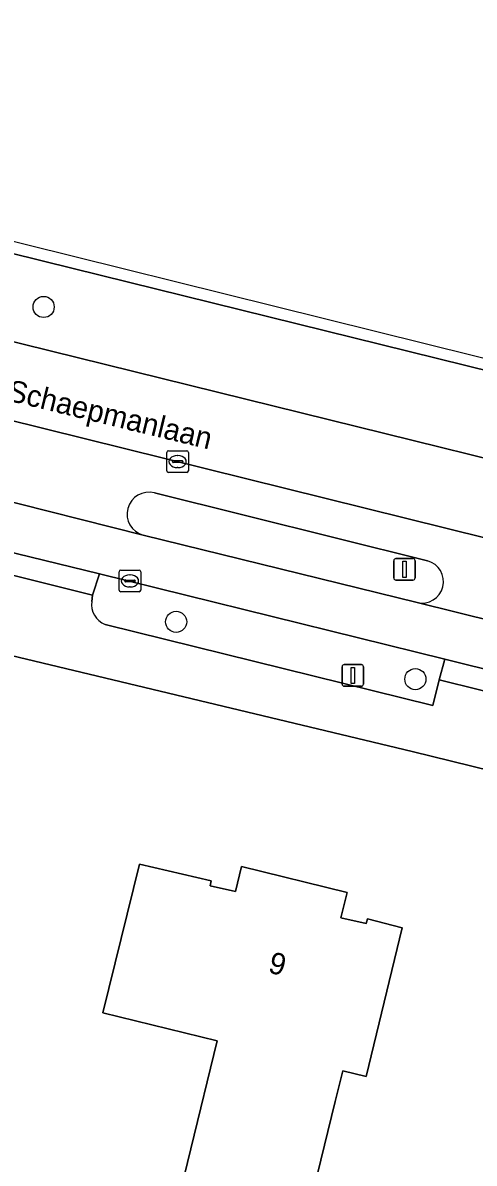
# Model space of a CAD drawing. Extents: x 161139 to 161601, y 381708 to 382245.
# Drawn here: x 161459.9 to 161480.8, y 382144.4 to 382197.2 of the extents above; entities that cross this region are included whole.
import ezdxf

# ---------------------------------------------------------------- set-up
doc = ezdxf.new("R2010")
doc.units = 0
for name, color, linetype in [('IMGEO_Berm_groen', 7, 'Continuous'), ('IMGEO_Boom', 7, 'Continuous'), ('IMGEO_Erf', 7, 'Continuous'), ('IMGEO_Fietspad_gesloten', 7, 'Continuous'), ('IMGEO_Kolk', 7, 'Continuous'), ('IMGEO_Lichtmast', 7, 'Continuous'), ('IMGEO_Openbare_ruimte_label', 7, 'Continuous'), ('IMGEO_Pand', 7, 'Continuous'), ('IMGEO_Pand_nummerreeks', 7, 'Continuous'), ('IMGEO_Parkeervlak_open', 7, 'Continuous'), ('IMGEO_Rijbaan_lokaal_gesloten', 7, 'Continuous'), ('IMGEO_Voetpad_open', 7, 'Continuous')]:
    doc.layers.add(name, color=color, linetype=linetype)

msp = doc.modelspace()

# ---------------------------------------------------------------- linework, layer by layer
at = {"layer": 'IMGEO_Berm_groen'}
for points in [[(161500, 382176.547), (161460.894, 382186.197), (161420.058, 382196.306), (161417.456, 382196.964), (161416.542, 382193.184), (161418.72, 382192.635), (161459.898, 382182.379), (161500, 382172.465), (161568.862, 382155.44)], [(161478.67, 382172.325), (161466.034, 382175.47)], [(161465.508, 382173.515), (161478.19, 382170.397)], [(161463.49, 382171.731), (161463.163, 382170.733), (161463.131, 382170.447)], [(161463.743, 382169.384), (161478.917, 382165.631), (161479.208, 382166.815), (161479.47, 382167.765), (161463.49, 382171.731)]]:
    msp.add_lwpolyline(points, dxfattribs=at)
for centre, radius, start, end in [((161465.777, 382174.491), 1.012, 75.2646, 254.6174), ((161478.421, 382171.363), 0.993, 256.5537, 75.4857), ((161464.108, 382170.302), 0.988, 171.548, 248.3126)]:
    msp.add_arc(centre, radius, start, end, dxfattribs=at)
at = {"layer": 'IMGEO_Boom'}
for centre in [(161460.901, 382184.081), (161467.035, 382169.5), (161478.112, 382166.848)]:
    msp.add_circle(centre, 0.489, dxfattribs=at)
at = {"layer": 'IMGEO_Erf'}
for points in [[(161553.295, 382144.911), (161544.61, 382147.101), (161500, 382158.072), (161477.956, 382163.494), (161457.897, 382168.303), (161418.52, 382178.097), (161389.844, 382185.251), (161387.058, 382185.651), (161384.186, 382184.996), (161381.949, 382183.375), (161380.259, 382181.034), (161377.586, 382172.934), (161374.321, 382163.969), (161372.26, 382158.835), (161369.98, 382153.637), (161365.084, 382143.565), (161365.175, 382143.293), (161389.855, 382127.317), (161408.789, 382114.947), (161450.498, 382088.211), (161500, 382056.07), (161523.437, 382040.853), (161561.628, 382099.383), (161581.409, 382129.761)], [(161466.492, 382140.097), (161468.93, 382150.099), (161463.637, 382151.397), (161465.343, 382158.285), (161468.656, 382157.507), (161468.609, 382157.277), (161469.778, 382157.019), (161470.062, 382158.175), (161474.951, 382156.972), (161474.663, 382155.802), (161475.834, 382155.531), (161475.889, 382155.744), (161477.505, 382155.333), (161475.828, 382148.441), (161474.75, 382148.705), (161474.406, 382147.295), (161473.571, 382143.873)]]:
    msp.add_lwpolyline(points, dxfattribs=at)
at = {"layer": 'IMGEO_Fietspad_gesloten'}
for points in [[(161388.471, 382194.662), (161386.139, 382191.421), (161400.157, 382187.686), (161402.771, 382186.995), (161404.125, 382186.632), (161408.543, 382185.44), (161420.035, 382182.5), (161423.68, 382181.579), (161459.001, 382172.814), (161463.49, 382171.731), (161479.47, 382167.765), (161485.068, 382166.376)], [(161487.403, 382168.106), (161478.19, 382170.397), (161465.508, 382173.515), (161458.283, 382175.333), (161426.145, 382183.304), (161418.85, 382185.12), (161410.964, 382187.154), (161404.025, 382189.049), (161403.898, 382189.082), (161400.753, 382189.896), (161395.77, 382191.23), (161389.063, 382193.224)]]:
    msp.add_lwpolyline(points, dxfattribs=at)
at = {"layer": 'IMGEO_Kolk'}
for p, q in [((161466.68, 382177.421), (161467.532, 382177.421)), ((161466.605, 382176.495), (161466.605, 382177.347)), ((161466.864, 382176.915), (161466.864, 382176.927)), ((161467.302, 382176.878), (161466.904, 382176.878)), ((161466.907, 382176.964), (161467.305, 382176.964)), ((161467.093, 382177.201), (161467.118, 382177.201)), ((161467.348, 382176.927), (161467.348, 382176.915)), ((161467.606, 382177.347), (161467.606, 382176.495)), ((161467.532, 382176.421), (161466.68, 382176.421)), ((161467.116, 382176.641), (161467.091, 382176.641)), ((161464.398, 382170.969), (161464.398, 382171.821)), ((161464.473, 382171.895), (161465.325, 382171.895)), ((161464.886, 382171.675), (161464.911, 382171.675)), ((161465.399, 382171.821), (161465.399, 382170.969)), ((161464.657, 382171.389), (161464.657, 382171.401)), ((161465.095, 382171.352), (161464.697, 382171.352)), ((161464.7, 382171.438), (161465.098, 382171.438)), ((161464.909, 382171.115), (161464.884, 382171.115)), ((161465.141, 382171.401), (161465.141, 382171.389)), ((161465.325, 382170.895), (161464.473, 382170.895))]:
    msp.add_line(p, q, dxfattribs=at)
for points in [[(161466.68, 382177.421), (161467.532, 382177.421)], [(161466.605, 382176.495), (161466.605, 382177.347)], [(161467.606, 382177.347), (161467.606, 382176.495)], [(161467.532, 382176.421), (161466.68, 382176.421)], [(161464.398, 382170.969), (161464.398, 382171.821)], [(161464.473, 382171.895), (161465.325, 382171.895)], [(161465.399, 382171.821), (161465.399, 382170.969)], [(161465.325, 382170.895), (161464.473, 382170.895)]]:
    msp.add_lwpolyline(points, dxfattribs=at)
for centre, radius, start, end in [((161466.682, 382177.345), 0.0765, 91.552, 178.448), ((161466.682, 382177.345), 0.0765, 91.552, 178.448), ((161467.53, 382177.345), 0.0765, 1.552, 88.448), ((161467.53, 382177.345), 0.0765, 1.552, 88.448), ((161466.904, 382176.924), 0.0403, 85.8775, 175.7526), ((161466.901, 382176.914), 0.0366, 178.938, 274.7102), ((161467.305, 382176.921), 0.043, 264.8664, 352.4533), ((161467.309, 382176.926), 0.0386, 1.7309, 96.639), ((161466.682, 382176.497), 0.0765, 181.552, 268.448), ((161466.682, 382176.497), 0.0765, 181.552, 268.448), ((161467.53, 382176.497), 0.0765, 271.552, 358.448), ((161467.53, 382176.497), 0.0765, 271.552, 358.448), ((161464.475, 382171.819), 0.0765, 91.552, 178.448), ((161464.475, 382171.819), 0.0765, 91.552, 178.448), ((161465.323, 382171.819), 0.0765, 1.552, 88.448), ((161465.323, 382171.819), 0.0765, 1.552, 88.448), ((161464.697, 382171.398), 0.0403, 85.8775, 175.7526), ((161464.694, 382171.388), 0.0366, 178.938, 274.7102), ((161465.098, 382171.395), 0.043, 264.8664, 352.4533), ((161465.102, 382171.4), 0.0386, 1.7309, 96.639), ((161464.475, 382170.971), 0.0765, 181.552, 268.448), ((161464.475, 382170.971), 0.0765, 181.552, 268.448), ((161465.323, 382170.971), 0.0765, 271.552, 358.448), ((161465.323, 382170.971), 0.0765, 271.552, 358.448)]:
    msp.add_arc(centre, radius, start, end, dxfattribs=at)
for centre, major_axis, ratio, start_param, end_param in [((161467.092, 382176.921), (-0.387, 0.002), 0.722429, 4.712389, 7.853982), ((161467.117, 382176.921), (-0.39, 0.002), 0.717154, 1.570796, 4.712389), ((161464.885, 382171.395), (-0.387, 0.002), 0.722429, 4.712389, 7.853982), ((161464.91, 382171.395), (-0.39, 0.002), 0.717154, 1.570796, 4.712389)]:
    msp.add_ellipse(centre, major_axis=major_axis, ratio=ratio, start_param=start_param, end_param=end_param, dxfattribs=at)
at = {"layer": 'IMGEO_Lichtmast'}
for p, q in [((161477.109, 382171.533), (161477.109, 382172.333)), ((161477.109, 382172.333), (161477.109, 382171.533)), ((161477.209, 382172.433), (161477.999, 382172.433)), ((161477.999, 382172.433), (161477.209, 382172.433)), ((161478.099, 382172.333), (161478.099, 382171.533)), ((161478.099, 382171.533), (161478.099, 382172.333)), ((161477.999, 382171.433), (161477.209, 382171.433)), ((161477.209, 382171.433), (161477.999, 382171.433)), ((161474.72, 382166.619), (161474.72, 382167.419)), ((161474.72, 382167.419), (161474.72, 382166.619)), ((161474.82, 382167.519), (161475.61, 382167.519)), ((161475.61, 382167.519), (161474.82, 382167.519)), ((161475.71, 382167.419), (161475.71, 382166.619)), ((161475.71, 382166.619), (161475.71, 382167.419)), ((161475.61, 382166.519), (161474.82, 382166.519)), ((161474.82, 382166.519), (161475.61, 382166.519))]:
    msp.add_line(p, q, dxfattribs=at)
for points in [[(161477.529, 382172.308), (161477.679, 382172.308), (161477.679, 382171.558), (161477.529, 382171.558), (161477.529, 382172.308)], [(161475.14, 382167.394), (161475.29, 382167.394), (161475.29, 382166.644), (161475.14, 382166.644), (161475.14, 382167.394)]]:
    msp.add_lwpolyline(points, dxfattribs=at)
for centre, start, end in [((161477.209, 382172.333), 90, 180), ((161477.209, 382172.333), 90, 180), ((161477.999, 382172.333), 0, 90), ((161477.999, 382172.333), 360, 90), ((161477.209, 382171.533), 180, 270), ((161477.209, 382171.533), 180, 270), ((161477.999, 382171.533), 270, 0), ((161477.999, 382171.533), 270, 0), ((161474.82, 382167.419), 90, 180), ((161474.82, 382167.419), 90, 180), ((161475.61, 382167.419), 0, 90), ((161475.61, 382167.419), 360, 90), ((161474.82, 382166.619), 180, 270), ((161474.82, 382166.619), 180, 270), ((161475.61, 382166.619), 270, 0), ((161475.61, 382166.619), 270, 0)]:
    msp.add_arc(centre, 0.1, start, end, dxfattribs=at)
at = {"layer": 'IMGEO_Pand'}
msp.add_lwpolyline([(161473.571, 382143.873), (161474.406, 382147.295), (161474.75, 382148.705), (161475.828, 382148.441), (161477.505, 382155.333), (161475.889, 382155.744), (161475.834, 382155.531), (161474.663, 382155.802), (161474.951, 382156.972), (161470.062, 382158.175), (161469.778, 382157.019), (161468.609, 382157.277), (161468.656, 382157.507), (161465.343, 382158.285), (161463.637, 382151.397), (161468.93, 382150.099), (161466.492, 382140.097)], dxfattribs=at)
at = {"layer": 'IMGEO_Parkeervlak_open'}
for points in [[(161502.587, 382168.125), (161500, 382168.766), (161459.102, 382178.908), (161420.449, 382188.487), (161415.442, 382189.785), (161412.878, 382190.505)], [(161458.283, 382175.333), (161465.508, 382173.515)], [(161466.034, 382175.47), (161478.67, 382172.325)], [(161478.19, 382170.397), (161487.403, 382168.106)]]:
    msp.add_lwpolyline(points, dxfattribs=at)
for centre, radius, start, end in [((161465.777, 382174.491), 1.012, 75.2646, 254.6174), ((161478.421, 382171.363), 0.993, 256.5537, 75.4857)]:
    msp.add_arc(centre, radius, start, end, dxfattribs=at)
at = {"layer": 'IMGEO_Rijbaan_lokaal_gesloten'}
for points in [[(161562.018, 382161.64), (161415.973, 382197.911), (161384.398, 382213.493), (161381.617, 382214.866), (161356.708, 382243.113)], [(161374.664, 382217.069), (161378.836, 382213.986), (161381.705, 382212.177), (161383.113, 382211.438), (161385.647, 382210.252), (161389.368, 382208.652), (161392.021, 382207.47), (161392.131, 382207.421), (161400.173, 382203.726), (161402.655, 382202.572), (161402.834, 382202.489), (161404.051, 382201.98), (161404.678, 382201.717), (161413.629, 382198.305), (161416.752, 382197.147), (161417.456, 382196.964), (161420.058, 382196.306), (161460.894, 382186.197), (161500, 382176.547)], [(161371.295, 382209.7), (161379.73, 382204.16), (161385.013, 382201.164), (161389.691, 382198.806), (161397.081, 382195.854), (161402.036, 382194.12), (161402.198, 382194.055), (161405.248, 382192.835), (161406.546, 382192.371), (161409.616, 382191.449), (161412.637, 382190.575), (161412.768, 382190.537), (161412.878, 382190.505), (161415.442, 382189.785), (161420.449, 382188.487), (161459.102, 382178.908), (161500, 382168.766), (161502.587, 382168.125), (161571.771, 382151.019), (161574.719, 382150.267), (161575.117, 382154.078)], [(161568.862, 382155.44), (161500, 382172.465), (161459.898, 382182.379), (161418.72, 382192.635), (161416.542, 382193.184)]]:
    msp.add_lwpolyline(points, dxfattribs=at)
at = {"layer": 'IMGEO_Voetpad_open'}
for points in [[(161378.971, 382187.245), (161387.058, 382185.651), (161389.844, 382185.251), (161418.52, 382178.097), (161457.897, 382168.303), (161477.956, 382163.494), (161500, 382158.072), (161544.61, 382147.101), (161553.295, 382144.911), (161577.621, 382138.939), (161579.137, 382138.37), (161582.049, 382137.272), (161581.211, 382138.152), (161576.782, 382142.804)], [(161463.131, 382170.447), (161463.163, 382170.733), (161458.766, 382171.826), (161458.712, 382171.632)], [(161484.784, 382165.147), (161484.817, 382165.422), (161479.208, 382166.815), (161478.917, 382165.631), (161463.743, 382169.384)]]:
    msp.add_lwpolyline(points, dxfattribs=at)
for points in [[(161458.766, 382171.826), (161463.163, 382170.733), (161463.49, 382171.731), (161459.001, 382172.814)], [(161479.47, 382167.765), (161479.208, 382166.815), (161484.817, 382165.422), (161485.068, 382166.376)]]:
    msp.add_lwpolyline(points, close=True, dxfattribs=at)
msp.add_arc((161464.108, 382170.302), 0.988, 171.548, 248.3126, dxfattribs=at)

# ---------------------------------------------------------------- texts
at = {"layer": 'IMGEO_Openbare_ruimte_label'}
msp.add_text('Dr Schaepmanlaan', height=1, rotation=346.3528, dxfattribs=at).set_placement((161457.435, 382180.183))
at = {"layer": 'IMGEO_Pand_nummerreeks'}
msp.add_text('9', height=1, rotation=345.6137, dxfattribs=at).set_placement((161471.252, 382153.275))

doc.saveas('drawing.dxf')
